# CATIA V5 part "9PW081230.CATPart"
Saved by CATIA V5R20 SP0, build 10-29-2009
Part number: 9PW081230
Revision: ANY
Definition: UNKNOWN
Nomenclature: 9PW081230
Source: Unknown
Bounding box of the stored display mesh (mm): x -174.5 to 0, y -11.573 to 4, z -6.1 to 6.1
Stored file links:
  C:\Users\Utente\Desktop\IO LAVORO\3D X SITO CF\CUMSA\3D files PW\pw081230\pw081230_ejection\9PW081230.CATPart
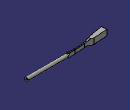
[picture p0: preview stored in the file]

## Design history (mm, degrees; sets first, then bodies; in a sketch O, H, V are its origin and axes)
Body1 "Chaflán2" (main body)
  Solid1: solid without history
